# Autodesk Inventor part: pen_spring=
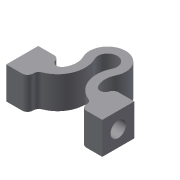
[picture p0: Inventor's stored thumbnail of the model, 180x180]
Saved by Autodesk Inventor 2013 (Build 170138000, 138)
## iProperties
Created: 2013-11
Part Number: pen_spring=
Material: Generic
Document SubType Name: Modeling
Designer: Jonas
Density: 1 g/cm^3
Author: Jonas
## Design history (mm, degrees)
sketch "Sketch1"
  geometry: L1 (5, 3)-(9, 3); L2 (9, 3)-(9, -3); L3 (9, -3)-(5, -3); L4 (5, -3)-(5, 3); 2 further points
  constraints: 8 end point, 2 parallel, 1 horizontal, 1 horizontal alignment, 1 midpoint, 1 perpendicular
  dimensions: "d0" = 4 distance of L1.start L1.end; "d2" = 6 distance of L1.end L2.end; "d3" = 9 distance from line of L2 point (0, 0)
extrude "Extrusion1" new body sketch "Sketch1" distance "d4" = 6; taper "d5" = 0 deg
sketch "Sketch2"
  geometry: L1 (9, 3)-(5, 3) reference; L2 (5, 3)-(5, -3) reference; L3 (5, -3)-(9, -3) reference; L4 (9, -3)-(9, 3) reference; L5 (0, 10.404)-(0, 8.804); L6 (5, -1.139)-(5, 0.532); A1 r 1.804 centre (0, 7) between (1.614, 6.193) and (0, 8.804); A2 r 5.17 centre (6.238, 3.881) between (1.614, 6.193) and (5, -1.139); A3 r 3.57 centre (6.238, 3.881) between (3.045, 5.478) and (5, 0.532); A4 r 3.404 centre (0, 7) between (3.045, 5.478) and (0, 10.404); 1 further point
  constraints: 8 point on circle, 4 centre point, 4 end point, 2 parallel, 2 point on line, 2 vertical alignment, 1 tangent, 1 other
  dimensions: "d6" = 1.6 radial gap between concentric circles of A4 A1
extrude "Extrusion2" join sketch "Sketch2" stored distance "d8" = 4; taper "d9" = 0 deg
fillet "Fillet1" dims "d10" = 1
sketch "Sketch3"
  geometry: L1 (0, 6)-(0, 0) reference; L2 (0, 0)-(-6, 0) reference; C1 r 1.45 at (-3, 3); 3 further points
  constraints: 2 midpoint, 1 centre point, 1 horizontal alignment, 1 vertical alignment
  dimensions: "d11" = 2.9 diameter of C1
extrude "Extrusion3" cut sketch "Sketch3" distance "d12" = 3; taper "d13" = 0 deg
mirror "Mirror1"
body "Solid1"
node "Projected Loop1"
